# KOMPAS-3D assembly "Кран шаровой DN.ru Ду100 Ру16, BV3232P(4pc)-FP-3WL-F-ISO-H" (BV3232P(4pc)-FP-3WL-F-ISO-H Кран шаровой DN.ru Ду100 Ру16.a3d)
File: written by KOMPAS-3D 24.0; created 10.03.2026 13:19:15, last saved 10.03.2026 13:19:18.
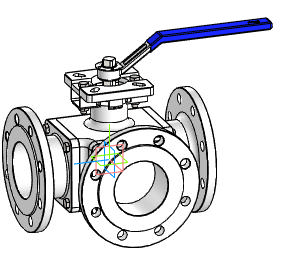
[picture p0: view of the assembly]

Document properties: Автор: R2D2; Полное имя файла: E:\Работа\Зайцев\BV3232P(4pc)-FP-3WL-F-ISO-H Кран шаровой DN.ru Ду15-100 Ру16\DN100\исходные материалы\BV3232P(4pc)-FP-3WL-F-ISO-H Кран шаровой DN.ru Ду100 Ру16.a3d

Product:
- Component [assembly]: Сборка1  | qty 1  | Масса: 49.43538; Автор: R2D2; source file: dn100_3d_step.a3d
- Part/product: Кран шаровой DN.ru Ду100 Ру16  | designation BV3232P(4pc)-FP-3WL-F-ISO-H
    Масса: 58.5
    Раздел спецификации: Прочие изделия
    Примечание: D160-36363

Referenced files in E:\Работа\Зайцев\BV3232P(4pc)-FP-3WL-F-ISO-H Кран шаровой DN.ru Ду15-100 Ру16\DN100\исходные материалы\: dn100_3d_step.a3d
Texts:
  BV3232P(4pc)-FP-3WL-F-ISO-H
  Сборка1 Сборка1
  Ось Z.Начало координат
  Ось Y.Начало координат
